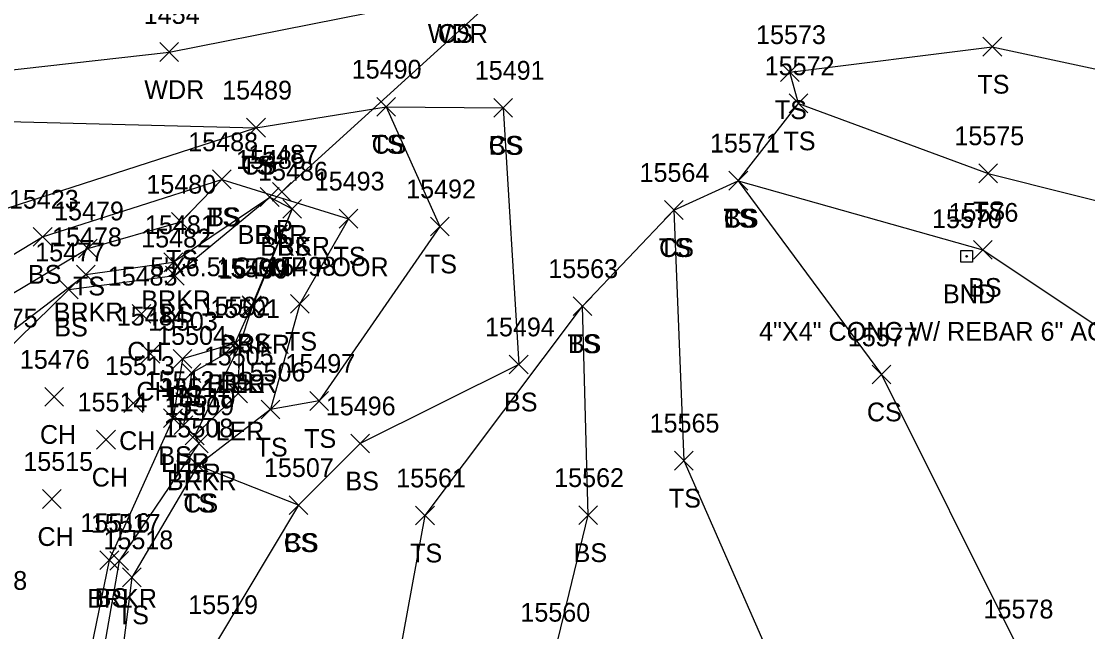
# Model space of a CAD drawing. Extents: x 1606530 to 1613020, y 784959 to 789666.
# Drawn here: x 1609153.1 to 1609266.7, y 788335.5 to 788400.5 of the extents above; entities that cross this region are included whole.
import ezdxf

# ---------------------------------------------------------------- set-up
doc = ezdxf.new("R2010")
doc.units = 0
for name, color, linetype in [('D_A', 7, 'Continuous'), ('D_C', 7, 'Continuous'), ('D_I', 7, 'Continuous'), ('D_TIC', 7, 'Continuous'), ('DCP', 7, 'Continuous'), ('L_A', 7, 'Continuous'), ('L_I', 7, 'Continuous'), ('L_TIC', 7, 'Continuous'), ('LARO', 7, 'Continuous'), ('LAWA', 7, 'Continuous'), ('LAWE', 7, 'Continuous'), ('LELB', 7, 'Continuous'), ('M_A', 7, 'Continuous'), ('M_C', 7, 'Continuous'), ('M_I', 7, 'Continuous'), ('MHBP', 7, 'Continuous')]:
    doc.layers.add(name, color=color, linetype=linetype)

msp = doc.modelspace()

# ---------------------------------------------------------------- linework, layer by layer
at = {"layer": 'D_TIC'}
for points in [[(1609179.84, 788381.35), (1609181.84, 788383.35)], [(1609181.84, 788381.35), (1609179.84, 788383.35)]]:
    msp.add_lwpolyline(points, dxfattribs=at)
at = {"layer": 'DCP'}
msp.add_lwpolyline([(1609180.84, 788382.35), (1609291.93, 788483.27)], dxfattribs=at)
at = {"layer": 'L_TIC'}
for points in [[(1609255.53, 788396.81), (1609257.53, 788398.81)], [(1609257.53, 788396.81), (1609255.53, 788398.81)], [(1609167.82, 788396.24), (1609169.82, 788398.24)], [(1609169.82, 788396.24), (1609167.82, 788398.24)], [(1609233.95, 788394.09), (1609235.95, 788396.09)], [(1609235.95, 788394.09), (1609233.95, 788396.09)], [(1609190.96, 788390.41), (1609192.96, 788392.41)], [(1609192.96, 788390.41), (1609190.96, 788392.41)], [(1609190.96, 788390.41), (1609192.96, 788392.41)], [(1609192.96, 788390.41), (1609190.96, 788392.41)], [(1609203.42, 788390.29), (1609205.42, 788392.29)], [(1609205.42, 788390.29), (1609203.42, 788392.29)], [(1609203.42, 788390.29), (1609205.42, 788392.29)], [(1609205.42, 788390.29), (1609203.42, 788392.29)], [(1609234.87, 788390.77), (1609236.87, 788392.77)], [(1609236.87, 788390.77), (1609234.87, 788392.77)], [(1609234.87, 788390.77), (1609236.87, 788392.77)], [(1609236.87, 788390.77), (1609234.87, 788392.77)], [(1609177.08, 788388.18), (1609179.08, 788390.18)], [(1609179.08, 788388.18), (1609177.08, 788390.18)], [(1609177.08, 788388.18), (1609179.08, 788390.18)], [(1609179.08, 788388.18), (1609177.08, 788390.18)], [(1609255.08, 788383.31), (1609257.08, 788385.31)], [(1609257.08, 788383.31), (1609255.08, 788385.31)], [(1609173.45, 788382.67), (1609175.45, 788384.67)], [(1609175.45, 788382.67), (1609173.45, 788384.67)], [(1609173.45, 788382.67), (1609175.45, 788384.67)], [(1609175.45, 788382.67), (1609173.45, 788384.67)], [(1609228.47, 788382.53), (1609230.47, 788384.53)], [(1609230.47, 788382.53), (1609228.47, 788384.53)], [(1609228.47, 788382.53), (1609230.47, 788384.53)], [(1609230.47, 788382.53), (1609228.47, 788384.53)], [(1609228.47, 788382.53), (1609230.47, 788384.53)], [(1609230.47, 788382.53), (1609228.47, 788384.53)], [(1609178.54, 788380.79), (1609180.54, 788382.79)], [(1609180.54, 788380.79), (1609178.54, 788382.79)], [(1609178.54, 788380.79), (1609180.54, 788382.79)], [(1609180.54, 788380.79), (1609178.54, 788382.79)], [(1609180.94, 788379.54), (1609182.94, 788381.54)], [(1609182.94, 788379.54), (1609180.94, 788381.54)], [(1609180.94, 788379.54), (1609182.94, 788381.54)], [(1609182.94, 788379.54), (1609180.94, 788381.54)], [(1609221.59, 788379.4), (1609223.59, 788381.4)], [(1609223.59, 788379.4), (1609221.59, 788381.4)], [(1609221.59, 788379.4), (1609223.59, 788381.4)], [(1609223.59, 788379.4), (1609221.59, 788381.4)], [(1609169.08, 788378.15), (1609171.08, 788380.15)], [(1609171.08, 788378.15), (1609169.08, 788380.15)], [(1609186.93, 788378.48), (1609188.93, 788380.48)], [(1609188.93, 788378.48), (1609186.93, 788380.48)], [(1609196.67, 788377.65), (1609198.67, 788379.65)], [(1609198.67, 788377.65), (1609196.67, 788379.65)], [(1609154.35, 788376.55), (1609156.35, 788378.55)], [(1609156.35, 788376.55), (1609154.35, 788378.55)], [(1609159.17, 788375.3), (1609161.17, 788377.3)], [(1609161.17, 788375.3), (1609159.17, 788377.3)], [(1609254.52, 788375.15), (1609256.52, 788377.15)], [(1609256.52, 788375.15), (1609254.52, 788377.15)], [(1609168.27, 788373.83), (1609170.27, 788375.83)], [(1609170.27, 788373.83), (1609168.27, 788375.83)], [(1609158.94, 788372.54), (1609160.94, 788374.54)], [(1609160.94, 788372.54), (1609158.94, 788374.54)], [(1609168.44, 788372.41), (1609170.44, 788374.41)], [(1609170.44, 788372.41), (1609168.44, 788374.41)], [(1609157.15, 788370.93), (1609159.15, 788372.93)], [(1609159.15, 788370.93), (1609157.15, 788372.93)], [(1609164.87, 788368.35), (1609166.87, 788370.35)], [(1609166.87, 788368.35), (1609164.87, 788370.35)], [(1609176.62, 788369.24), (1609178.62, 788371.24)], [(1609178.62, 788369.24), (1609176.62, 788371.24)], [(1609176.68, 788369.1), (1609178.68, 788371.1)], [(1609178.68, 788369.1), (1609176.68, 788371.1)], [(1609181.76, 788369.41), (1609183.76, 788371.41)], [(1609183.76, 788369.41), (1609181.76, 788371.41)], [(1609211.86, 788369.15), (1609213.86, 788371.15)], [(1609213.86, 788369.15), (1609211.86, 788371.15)], [(1609211.86, 788369.15), (1609213.86, 788371.15)], [(1609213.86, 788369.15), (1609211.86, 788371.15)], [(1609174.84, 788365.16), (1609176.84, 788367.16)], [(1609176.84, 788365.16), (1609174.84, 788367.16)], [(1609175.3, 788364.9), (1609177.3, 788366.9)], [(1609177.3, 788364.9), (1609175.3, 788366.9)], [(1609175.3, 788364.9), (1609177.3, 788366.9)], [(1609177.3, 788364.9), (1609175.3, 788366.9)], [(1609175.3, 788364.9), (1609177.3, 788366.9)], [(1609177.3, 788364.9), (1609175.3, 788366.9)], [(1609165.84, 788364.09), (1609167.84, 788366.09)], [(1609167.84, 788364.09), (1609165.84, 788366.09)], [(1609169.24, 788363.55), (1609171.24, 788365.55)], [(1609171.24, 788363.55), (1609169.24, 788365.55)], [(1609205.07, 788362.94), (1609207.07, 788364.94)], [(1609207.07, 788362.94), (1609205.07, 788364.94)], [(1609170.21, 788362.03), (1609172.21, 788364.03)], [(1609172.21, 788362.03), (1609170.21, 788364.03)], [(1609243.73, 788361.88), (1609245.73, 788363.88)], [(1609245.73, 788361.88), (1609243.73, 788363.88)], [(1609155.57, 788359.48), (1609157.57, 788361.48)], [(1609157.57, 788359.48), (1609155.57, 788361.48)], [(1609175.19, 788359.84), (1609177.19, 788361.84)], [(1609177.19, 788359.84), (1609175.19, 788361.84)], [(1609164.01, 788358.82), (1609166.01, 788360.82)], [(1609166.01, 788358.82), (1609164.01, 788360.82)], [(1609178.63, 788358.13), (1609180.63, 788360.13)], [(1609180.63, 788358.13), (1609178.63, 788360.13)], [(1609178.63, 788358.13), (1609180.63, 788360.13)], [(1609180.63, 788358.13), (1609178.63, 788360.13)], [(1609183.8, 788359.05), (1609185.8, 788361.05)], [(1609185.8, 788359.05), (1609183.8, 788361.05)], [(1609168.24, 788357.22), (1609170.24, 788359.22)], [(1609170.24, 788357.22), (1609168.24, 788359.22)], [(1609169.35, 788356.48), (1609171.35, 788358.48)], [(1609171.35, 788356.48), (1609169.35, 788358.48)], [(1609169.35, 788356.48), (1609171.35, 788358.48)], [(1609171.35, 788356.48), (1609169.35, 788358.48)], [(1609161.1, 788354.93), (1609163.1, 788356.93)], [(1609163.1, 788354.93), (1609161.1, 788356.93)], [(1609170.55, 788355.38), (1609172.55, 788357.38)], [(1609172.55, 788355.38), (1609170.55, 788357.38)], [(1609170.99, 788354.54), (1609172.99, 788356.54)], [(1609172.99, 788354.54), (1609170.99, 788356.54)], [(1609188.17, 788354.52), (1609190.17, 788356.52)], [(1609190.17, 788354.52), (1609188.17, 788356.52)], [(1609222.66, 788352.69), (1609224.66, 788354.69)], [(1609224.66, 788352.69), (1609222.66, 788354.69)], [(1609170.89, 788352.17), (1609172.89, 788354.17)], [(1609172.89, 788352.17), (1609170.89, 788354.17)], [(1609170.89, 788352.17), (1609172.89, 788354.17)], [(1609172.89, 788352.17), (1609170.89, 788354.17)], [(1609155.32, 788348.6), (1609157.32, 788350.6)], [(1609157.32, 788348.6), (1609155.32, 788350.6)], [(1609181.6, 788347.95), (1609183.6, 788349.95)], [(1609183.6, 788347.95), (1609181.6, 788349.95)], [(1609181.6, 788347.95), (1609183.6, 788349.95)], [(1609183.6, 788347.95), (1609181.6, 788349.95)], [(1609195.09, 788346.84), (1609197.09, 788348.84)], [(1609197.09, 788346.84), (1609195.09, 788348.84)], [(1609212.48, 788346.88), (1609214.48, 788348.88)], [(1609214.48, 788346.88), (1609212.48, 788348.88)], [(1609161.45, 788342.09), (1609163.45, 788344.09)], [(1609163.45, 788342.09), (1609161.45, 788344.09)], [(1609162.51, 788342.02), (1609164.51, 788344.02)], [(1609164.51, 788342.02), (1609162.51, 788344.02)], [(1609163.85, 788340.25), (1609165.85, 788342.25)], [(1609165.85, 788340.25), (1609163.85, 788342.25)]]:
    msp.add_lwpolyline(points, dxfattribs=at)
at = {"layer": 'LARO'}
for points in [[(1609176.3, 788365.9), (1609171.21, 788363.03), (1609170.35, 788357.48)], [(1609176.3, 788365.9), (1609176.19, 788360.84), (1609171.55, 788356.38), (1609170.35, 788357.48)]]:
    msp.add_lwpolyline(points, dxfattribs=at)
at = {"layer": 'LAWA'}
msp.add_lwpolyline([(1609030.56, 788292.64), (1609056.03, 788324.44), (1609082.56, 788354.61), (1609090.16, 788369.42), (1609097.26, 788381.32), (1609109.23, 788386.03), (1609115.48, 788389.16), (1609124.65, 788392.27), (1609168.82, 788397.24), (1609199.02, 788403.22), (1609247.62, 788406.18), (1609289.08, 788410.02), (1609331.31, 788409.89), (1609380.07, 788411.97), (1609422.47, 788410.64), (1609441.9, 788412.64), (1609456.94, 788393.19), (1609459.97, 788389.84), (1609451.94, 788379.3), (1609445.61, 788371.6)], dxfattribs=at)
at = {"layer": 'LAWE'}
for points in [[(1609173.65, 788240.68), (1609157.57, 788256.3), (1609146.8, 788268.87), (1609140.11, 788290.97), (1609139.76, 788302.75), (1609129.69, 788311.81), (1609128.89, 788332.92), (1609134.82, 788352.28), (1609140.94, 788359.53), (1609147.89, 788364.33), (1609159.94, 788373.54), (1609169.27, 788374.83), (1609179.54, 788381.79), (1609181.94, 788380.54), (1609177.68, 788370.1), (1609176.3, 788365.9)], [(1609176.3, 788365.9), (1609171.55, 788356.38)], [(1609171.99, 788355.54), (1609163.51, 788343.02), (1609160.55, 788326.15), (1609159.75, 788312.64), (1609162.58, 788294.54), (1609165.68, 788272.74), (1609187.56, 788248.97)], [(1609171.99, 788355.54), (1609171.55, 788356.38)]]:
    msp.add_lwpolyline(points, dxfattribs=at)
at = {"layer": 'LELB'}
for points in [[(1609229.47, 788383.53), (1609235.87, 788391.77), (1609234.95, 788395.09), (1609256.53, 788397.81), (1609290, 788390.61), (1609315.27, 788387.55), (1609343.3, 788388.82), (1609351.97, 788404.1), (1609376.56, 788405.69), (1609392.36, 788394.13), (1609429.62, 788393.16), (1609442.68, 788388.57), (1609459.97, 788389.84), (1609474.42, 788390.35), (1609486.77, 788400.06), (1609484.73, 788410.56), (1609507.1, 788413.97), (1609507.85, 788418.71)], [(1609065.63, 788267.33), (1609081.96, 788290.89), (1609101.74, 788313.34), (1609121.94, 788328.84), (1609120.75, 788351.64), (1609128.03, 788374.5), (1609144.73, 788378.4), (1609178.08, 788389.18), (1609191.96, 788391.41), (1609197.67, 788378.65), (1609184.8, 788360.05), (1609179.63, 788359.13)], [(1609204.42, 788391.29), (1609206.07, 788363.94), (1609189.17, 788355.52), (1609182.6, 788348.95), (1609173.89, 788334.34), (1609176.46, 788313.19), (1609162.61, 788310.85)], [(1609191.96, 788391.41), (1609204.42, 788391.29)], [(1609235.87, 788391.77), (1609256.08, 788384.31), (1609291.75, 788375.34), (1609316.49, 788370.01), (1609344.99, 788380.11), (1609370.61, 788379.55), (1609398.08, 788381.21), (1609428.47, 788380.83), (1609442.68, 788388.57)], [(1609053.66, 788273.38), (1609077.55, 788293.59), (1609095.85, 788318.07), (1609115.19, 788336.22), (1609111.13, 788353.77), (1609121.97, 788374.07), (1609132.13, 788390.34), (1609178.08, 788389.18)], [(1609081.23, 788263.4), (1609089.39, 788281.95), (1609107.58, 788302.23), (1609121.69, 788312.33), (1609125.65, 788321.26), (1609126.42, 788350.58), (1609137.6, 788366.8), (1609155.35, 788377.55), (1609174.45, 788383.67)], [(1609127.26, 788334.06), (1609133.18, 788354.35), (1609139.29, 788361.81), (1609148.3, 788369.22), (1609160.17, 788376.3), (1609170.08, 788379.15), (1609174.45, 788383.67), (1609187.93, 788379.48), (1609182.76, 788370.41), (1609179.63, 788359.13), (1609171.89, 788353.17), (1609164.85, 788341.25), (1609162.76, 788324.69)], [(1609222.59, 788380.4), (1609229.47, 788383.53), (1609244.73, 788362.88), (1609259.19, 788333.87), (1609270.6, 788307.32)], [(1609229.47, 788383.53), (1609255.52, 788376.15), (1609272.39, 788364.9), (1609284.87, 788359.31), (1609322.96, 788353.08), (1609327.57, 788340.07)], [(1609174.2, 788240.79), (1609158.08, 788257.45), (1609147.39, 788269.58), (1609141.26, 788291.02), (1609140.39, 788303.27), (1609130.33, 788311.97), (1609130.92, 788333.58), (1609136.63, 788350.87), (1609143.46, 788357.67), (1609150.97, 788364.89), (1609158.15, 788371.93), (1609169.44, 788373.41), (1609179.54, 788381.79)], [(1609181.94, 788380.54), (1609177.62, 788370.24), (1609175.84, 788366.16), (1609170.24, 788364.55), (1609169.24, 788358.22), (1609162.45, 788343.09), (1609158.86, 788325.59), (1609159.24, 788313.17), (1609161.54, 788294.45), (1609164.83, 788271.75), (1609186.74, 788246.08)], [(1609190.64, 788317.95), (1609196.09, 788347.84), (1609212.86, 788370.15), (1609222.59, 788380.4), (1609223.66, 788353.69), (1609238.31, 788320.33), (1609251.53, 788294.03), (1609264.47, 788265.1)], [(1609225.18, 788282.55), (1609218.63, 788304.57), (1609211.72, 788324.3), (1609209.98, 788333.53), (1609213.48, 788347.88), (1609212.86, 788370.15)], [(1609182.6, 788348.95), (1609171.89, 788353.17)]]:
    msp.add_lwpolyline(points, dxfattribs=at)
at = {"layer": 'MHBP'}
msp.add_lwpolyline([(1609253.16, 788376.09), (1609254.41, 788376.09), (1609254.41, 788374.84), (1609253.16, 788374.84)], close=True, dxfattribs=at)
msp.add_circle((1609253.79, 788375.47), 0.0833, dxfattribs=at)

# ---------------------------------------------------------------- texts
at = {"layer": 'D_A'}
msp.add_text('P', height=2, dxfattribs=at).set_placement((1609180.21, 788377.35))
at = {"layer": 'D_C'}
msp.add_text("5'X6.5' CGMP POOR", height=2, dxfattribs=at).set_placement((1609166.81, 788373.35))
at = {"layer": 'D_I'}
msp.add_text('15487', height=2, dxfattribs=at).set_placement((1609177.25, 788385.35))
at = {"layer": 'L_A'}
for s, p in [('WDR', (1609196.39, 788398.22)), ('CS', (1609197.46, 788398.22)), ('WDR', (1609166.18, 788392.24)), ('TS', (1609254.94, 788392.81)), ('TS', (1609233.36, 788390.09)), ('TS', (1609234.28, 788386.77)), ('TS', (1609234.28, 788386.77)), ('TS', (1609190.37, 788386.41)), ('CS', (1609190.4, 788386.41)), ('CS', (1609202.86, 788386.29)), ('BS', (1609202.86, 788386.29)), ('TS', (1609176.49, 788384.18)), ('CS', (1609176.52, 788384.18)), ('TS', (1609172.86, 788378.67)), ('BS', (1609172.89, 788378.67)), ('TS', (1609227.88, 788378.53)), ('CS', (1609227.91, 788378.53)), ('BS', (1609227.91, 788378.53)), ('TS', (1609254.49, 788379.31)), ('BRKR', (1609176.13, 788376.79)), ('BS', (1609177.98, 788376.79)), ('BRKR', (1609178.53, 788375.54)), ('BS', (1609180.38, 788375.54)), ('TS', (1609221, 788375.4)), ('CS', (1609221.03, 788375.4)), ('TS', (1609168.49, 788374.15)), ('TS', (1609186.34, 788374.48)), ('TS', (1609196.08, 788373.65)), ('BS', (1609153.79, 788372.55)), ('TS', (1609158.58, 788371.3)), ('BS', (1609253.96, 788371.15)), ('BRKR', (1609165.86, 788369.83)), ('BRKR', (1609156.53, 788368.54)), ('BS', (1609167.88, 788368.41)), ('BS', (1609156.59, 788366.93)), ('BRKR', (1609174.27, 788365.1)), ('BS', (1609176.06, 788365.24)), ('TS', (1609181.17, 788365.41)), ('TS', (1609211.27, 788365.15)), ('BS', (1609211.3, 788365.15)), ('CH', (1609164.36, 788364.35)), ('BRKR', (1609172.89, 788360.9)), ('LER', (1609173.88, 788360.9)), ('LEL', (1609173.94, 788360.9)), ('BS', (1609174.28, 788361.16)), ('CH', (1609165.33, 788360.09)), ('BS', (1609168.68, 788359.55)), ('BS', (1609204.51, 788358.94)), ('LEL', (1609168.85, 788358.03)), ('CS', (1609243.17, 788357.88)), ('LER', (1609173.77, 788355.84)), ('CH', (1609155.06, 788355.48)), ('CH', (1609163.5, 788354.82)), ('TS', (1609183.21, 788355.05)), ('TS', (1609178.04, 788354.13)), ('TS', (1609178.04, 788354.13)), ('BS', (1609167.68, 788353.22)), ('LER', (1609167.94, 788352.48)), ('LEL', (1609167.99, 788352.48)), ('LER', (1609169.13, 788351.38)), ('CH', (1609160.58, 788350.93)), ('BRKR', (1609168.58, 788350.54)), ('BS', (1609187.61, 788350.52)), ('TS', (1609170.3, 788348.17)), ('CS', (1609170.33, 788348.17)), ('TS', (1609222.07, 788348.69)), ('CH', (1609154.8, 788344.6)), ('CS', (1609181.04, 788343.95)), ('BS', (1609181.04, 788343.95)), ('TS', (1609194.5, 788342.84)), ('BS', (1609211.92, 788342.88)), ('BRKR', (1609160.1, 788338.02)), ('BS', (1609160.89, 788338.09)), ('TS', (1609163.26, 788336.25))]:
    msp.add_text(s, height=2, dxfattribs=at).set_placement(p)
at = {"layer": 'L_I'}
for s, p in [('1454', (1609166.12, 788400.24)), ('15573', (1609231.36, 788398.09)), ('15490', (1609188.28, 788394.41)), ('15490', (1609188.28, 788394.41)), ('15572', (1609232.28, 788394.77)), ('15572', (1609232.28, 788394.77)), ('15491', (1609201.39, 788394.29)), ('15491', (1609201.39, 788394.29)), ('15489', (1609174.48, 788392.18)), ('15489', (1609174.48, 788392.18)), ('15488', (1609170.86, 788386.67)), ('15488', (1609170.86, 788386.67)), ('15571', (1609226.45, 788386.53)), ('15571', (1609226.45, 788386.53)), ('15571', (1609226.45, 788386.53)), ('15575', (1609252.49, 788387.31)), ('15485', (1609175.95, 788384.79)), ('15485', (1609175.95, 788384.79)), ('15486', (1609178.3, 788383.54)), ('15486', (1609178.3, 788383.54)), ('15564', (1609218.95, 788383.4)), ('15564', (1609218.95, 788383.4)), ('15480', (1609166.4, 788382.15)), ('15493', (1609184.34, 788382.48)), ('15492', (1609194.08, 788381.65)), ('15423', (1609151.76, 788380.55)), ('15479', (1609156.57, 788379.3)), ('15576', (1609251.87, 788379.15)), ('15481', (1609166.25, 788377.83)), ('15478', (1609156.35, 788376.54)), ('15482', (1609165.85, 788376.41)), ('15477', (1609154.56, 788374.93)), ('15500', (1609173.87, 788373.24)), ('15499', (1609174.09, 788373.1)), ('15498', (1609179.17, 788373.41)), ('15563', (1609209.22, 788373.15)), ('15563', (1609209.22, 788373.15)), ('15483', (1609162.28, 788372.35)), ('15502', (1609172.17, 788369.16)), ('15501', (1609173.2, 788368.9)), ('15501', (1609173.2, 788368.9)), ('15501', (1609173.2, 788368.9)), ('15475', (1609147.38, 788367.89)), ('15475', (1609147.38, 788367.89)), ('15484', (1609163.25, 788368.09)), ('15503', (1609166.57, 788367.55)), ('15504', (1609167.55, 788366.03)), ('15494', (1609202.48, 788366.94)), ('15577', (1609241.14, 788365.88)), ('15505', (1609172.52, 788363.84)), ('15476', (1609152.92, 788363.48)), ('15513', (1609161.99, 788362.82)), ('15497', (1609181.21, 788363.05)), ('15506', (1609175.91, 788362.13)), ('15506', (1609175.91, 788362.13)), ('15512', (1609166.22, 788361.22)), ('15511', (1609167.9, 788360.48)), ('15511', (1609167.9, 788360.48)), ('15510', (1609168.44, 788359.38)), ('15514', (1609159.07, 788358.93)), ('15509', (1609168.31, 788358.54)), ('15496', (1609185.52, 788358.52)), ('15508', (1609168.22, 788356.17)), ('15508', (1609168.22, 788356.17)), ('15565', (1609220.02, 788356.69)), ('15515', (1609153.29, 788352.6)), ('15507', (1609178.93, 788351.95)), ('15507', (1609178.93, 788351.95)), ('15561', (1609193.02, 788350.84)), ('15562', (1609209.85, 788350.88)), ('15516', (1609159.37, 788346.09)), ('15517', (1609160.48, 788346.02)), ('15518', (1609161.83, 788344.25)), ('15468', (1609146.26, 788339.92)), ('15519', (1609170.86, 788337.34)), ('15560', (1609206.25, 788336.53)), ('15578', (1609255.6, 788336.87))]:
    msp.add_text(s, height=2, dxfattribs=at).set_placement(p)
at = {"layer": 'M_A'}
msp.add_text('BND', height=2, dxfattribs=at).set_placement((1609251.28, 788370.47))
at = {"layer": 'M_C'}
msp.add_text('4"X4" CONC W/ REBAR 6" AGS', height=2, dxfattribs=at).set_placement((1609231.68, 788366.47))
at = {"layer": 'M_I'}
msp.add_text('15570', height=2, dxfattribs=at).set_placement((1609250.11, 788378.47))

doc.saveas('drawing.dxf')
